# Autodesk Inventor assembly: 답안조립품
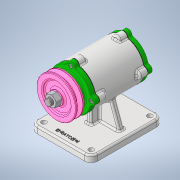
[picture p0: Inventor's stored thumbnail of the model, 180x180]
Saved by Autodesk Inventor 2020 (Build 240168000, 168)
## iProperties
Created: 2022-11
Part Number: 답안조립품
Document SubType Name: Assembly
Designer: owner
Author: owner
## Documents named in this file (12)
- C:\Users\owner\Desktop\721108V1008\답안조립품.iam
- C:\Users\owner\Desktop\721108V1008\본체.ipt
- C:\Users\owner\Desktop\721108V1008\V-벨트풀리.ipt
- C:\Users\owner\Desktop\721108V1008\개스킷.ipt
- C:\Users\owner\Desktop\721108V1008\너트 M12 x 1.25.ipt
- C:\Users\owner\Desktop\721108V1008\뒤커버.ipt
- C:\Users\owner\Desktop\721108V1008\베어링 6204.ipt
- C:\Users\owner\Desktop\721108V1008\볼트 M4 x 12.ipt
- C:\Users\owner\Desktop\721108V1008\앞커버.ipt
- C:\Users\owner\Desktop\721108V1008\오일 실.ipt
- C:\Users\owner\Desktop\721108V1008\축.ipt
- C:\Users\owner\Desktop\721108V1008\키 4 x 4.ipt
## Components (8 placed, 6 different names)
1. V-벨트풀리:1
2. 개스킷:1
3. KS B 1012 클래스 1 일반 - 미터 M12x1.25:1
4. KS B 2023 6204 - 20 x 47 x 14:1
5. KS B 2804 D D - 20 32 8:1
6. KS B 1311 (I) 4 x 4 x 12:1
7. 개스킷:2
8. KS B 2023 6204 - 20 x 47 x 14:2
